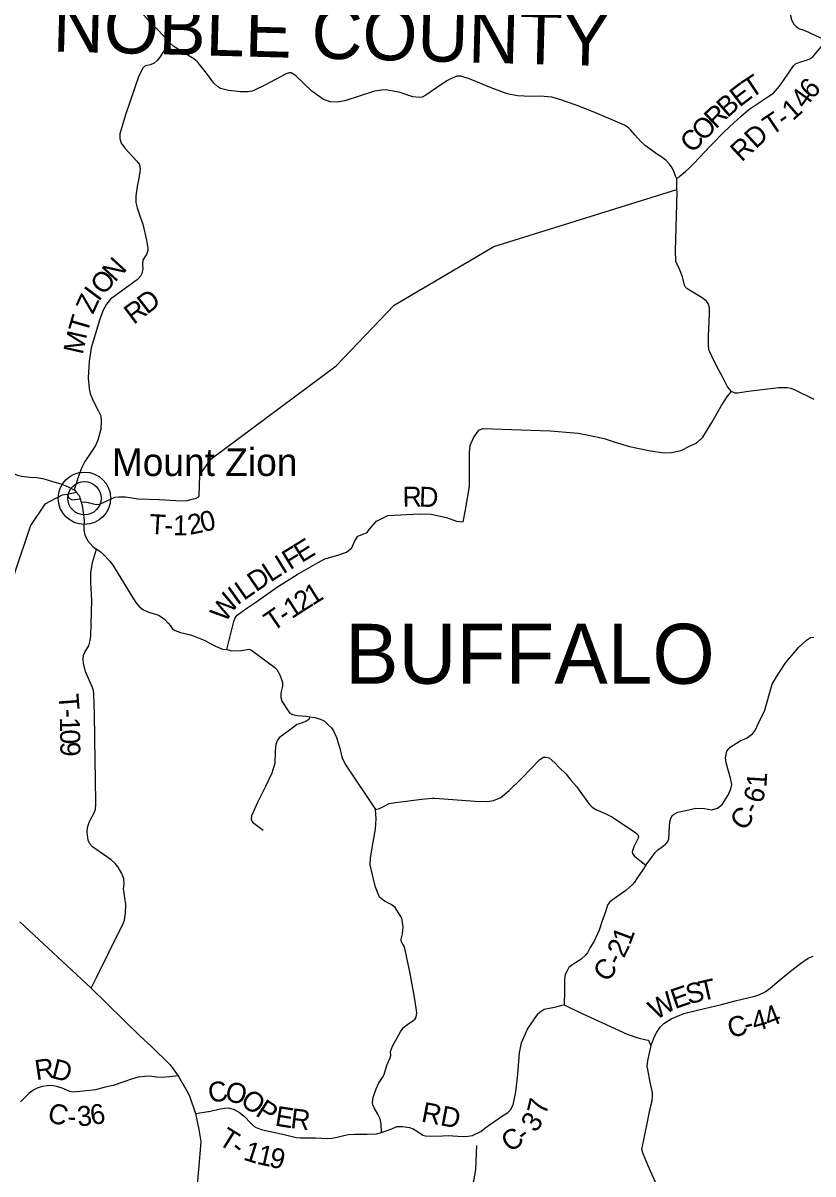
# Model space of a CAD drawing. Extents: x -22 to 431, y -18 to 160.
# Drawn here: x 324.981 to 327.228, y 153.438 to 156.71 of the extents above; entities that cross this region are included whole.
import ezdxf

# ---------------------------------------------------------------- set-up
doc = ezdxf.new("R2010")
doc.units = 0
for name, color, linetype in [('GM_X_Adjacent_County', 7, 'Continuous'), ('GM_X_Adjacent_County_Text', 7, 'Continuous'), ('GM_X_City_Street', 7, 'Continuous'), ('GM_X_City_Street_Text', 7, 'Continuous'), ('GM_X_County_Road', 7, 'Continuous'), ('GM_X_County_Road_Text', 7, 'Continuous'), ('GM_X_County_ROW', 7, 'Continuous'), ('GM_X_Minor_River_Text', 7, 'Continuous'), ('GM_X_Township_Road', 7, 'Continuous'), ('GM_X_Unincorporated_Text', 7, 'Continuous')]:
    doc.layers.add(name, color=color, linetype=linetype)

msp = doc.modelspace()

# ---------------------------------------------------------------- linework, layer by layer
at = {"layer": 'GM_X_Adjacent_County_Text'}
for points in [[(327.2309, 155.64), (327.1774, 155.6661), (327.1657, 155.6708), (327.1532, 155.6736), (327.1297, 155.6728), (327.0443, 155.6625), (327.0131, 155.658), (327.0056, 155.6584), (326.9958, 155.6627), (326.9909, 155.6681), (326.9846, 155.6758), (326.9701, 155.7048), (326.9542, 155.7342), (326.9409, 155.761), (326.9328, 155.7789), (326.9307, 155.7911), (326.9303, 155.8203), (326.933, 155.8836), (326.9336, 155.9007), (326.9318, 155.9076), (326.9296, 155.9129), (326.9244, 155.9209), (326.9124, 155.9291), (326.8763, 155.9508), (326.8688, 155.9558), (326.865, 155.9597), (326.8624, 155.9646), (326.8563, 155.9886), (326.8515, 156.0012), (326.8453, 156.0168), (326.8394, 156.0279), (326.8379, 156.0329), (326.8368, 156.0625), (326.8412, 156.2294), (326.841, 156.237), (326.8407, 156.2506), (326.8402, 156.267), (326.8369, 156.275), (326.8328, 156.286), (326.8269, 156.2983), (326.8199, 156.309), (326.8098, 156.3194), (326.7951, 156.3309), (326.7827, 156.3387), (326.7643, 156.3518), (326.7515, 156.3615), (326.7369, 156.3746), (326.7209, 156.3926), (326.71, 156.4053), (326.7033, 156.4122), (326.692, 156.4199), (326.6072, 156.4563), (326.554, 156.4767), (326.5083, 156.4929), (326.4849, 156.4996), (326.453, 156.5023), (326.4257, 156.5014), (326.3876, 156.5037), (326.3578, 156.5093), (326.3129, 156.5256), (326.2531, 156.5505), (326.2267, 156.5595), (326.215, 156.5592), (326.2002, 156.5529), (326.1865, 156.5455), (326.1572, 156.526), (326.1271, 156.5055), (326.1165, 156.4999), (326.1074, 156.4981), (326.0896, 156.5009), (326.0542, 156.5126), (326.0342, 156.517), (326.0135, 156.5202), (326.0006, 156.5192), (325.9813, 156.5164), (325.8967, 156.4895), (325.8736, 156.4852), (325.8555, 156.4858), (325.8355, 156.4928), (325.8029, 156.5166), (325.7572, 156.5599), (325.7485, 156.566), (325.7437, 156.5684), (325.7384, 156.5688), (325.7293, 156.5662), (325.6692, 156.5338), (325.6396, 156.519), (325.6327, 156.5164), (325.6218, 156.515), (325.5998, 156.5148), (325.5659, 156.5185), (325.5432, 156.5244), (325.5342, 156.5298), (325.5241, 156.5394), (325.5032, 156.5677), (325.4846, 156.5917), (325.4771, 156.6002), (325.467, 156.6086), (325.4407, 156.6248), (325.4106, 156.644), (325.3975, 156.6548), (325.3852, 156.6689), (325.3601, 156.6961), (325.3182, 156.7389)], [(324.78, 155.5591), (324.7845, 155.547), (324.79, 155.5302), (324.7951, 155.5181), (324.8026, 155.5055), (324.8157, 155.4944), (324.8401, 155.4816), (324.8714, 155.4669), (324.9022, 155.4537), (324.9477, 155.4324), (324.9658, 155.4247), (324.9768, 155.4219), (325.0005, 155.4194), (325.0206, 155.4181), (325.0376, 155.4152), (325.0628, 155.4078), (325.0922, 155.3992), (325.1095, 155.3918), (325.1197, 155.3871), (325.1266, 155.3827), (325.1334, 155.3754), (325.141, 155.3672), (325.1441, 155.3573), (325.1469, 155.3484)], [(325.1469, 155.3484), (325.1493, 155.3382), (325.1532, 155.3125), (325.155, 155.2978), (325.1542, 155.2784), (325.154, 155.2689), (325.1568, 155.2553), (325.1643, 155.2391), (325.1801, 155.2224), (325.1905, 155.2142), (325.1997, 155.2087), (325.2093, 155.2005), (325.2278, 155.1807), (325.2383, 155.1657), (325.2515, 155.1444), (325.2675, 155.1196), (325.2889, 155.084), (325.3022, 155.0626), (325.3111, 155.0525), (325.3222, 155.0428), (325.3409, 155.0341), (325.3618, 155.0291), (325.3687, 155.0259), (325.3837, 155.0151), (325.3937, 155.0043), (325.4003, 154.9961), (325.4057, 154.9886), (325.4141, 154.9834), (325.429, 154.9776), (325.4579, 154.9709), (325.4682, 154.967), (325.4964, 154.9561), (325.5289, 154.9385), (325.5488, 154.9301), (325.5605, 154.9288), (325.5753, 154.9256), (325.603, 154.9261), (325.6185, 154.9294), (325.6237, 154.9303), (325.6314, 154.927), (325.654, 154.9107), (325.6977, 154.8785), (325.7035, 154.8726), (325.7117, 154.8568), (325.7165, 154.8436), (325.7189, 154.8357), (325.7191, 154.8251), (325.7156, 154.8094), (325.7142, 154.8011), (325.7147, 154.7931), (325.7176, 154.7822), (325.7394, 154.7496), (325.7474, 154.7444), (325.7611, 154.742), (325.7869, 154.7398), (325.7967, 154.7381), (325.8108, 154.7361), (325.8275, 154.731), (325.839, 154.7259), (325.8486, 154.7162), (325.8583, 154.7062), (325.8641, 154.6979), (325.8731, 154.6791), (325.8827, 154.649), (325.8869, 154.6274), (325.8897, 154.6184), (325.8991, 154.6003), (325.9841, 154.4744), (325.9948, 154.4773), (326.0143, 154.4871), (326.0229, 154.491), (326.0407, 154.4944), (326.1151, 154.5033), (326.1439, 154.5061), (326.1526, 154.507), (326.2667, 154.4977), (326.3023, 154.4972), (326.3193, 154.5002), (326.34, 154.5085), (326.3635, 154.5283), (326.3989, 154.5627), (326.451, 154.6163), (326.4619, 154.623), (326.4676, 154.6234), (326.4774, 154.621), (326.4932, 154.6072), (326.5052, 154.5945), (326.5262, 154.5749), (326.5396, 154.5579), (326.5553, 154.5394), (326.5909, 154.4899), (326.5997, 154.4809), (326.61, 154.4741), (326.637, 154.4626), (326.6466, 154.4585), (326.6576, 154.4528), (326.7243, 154.4082), (326.73, 154.4021), (326.7316, 154.3976), (326.7309, 154.3926), (326.7185, 154.3679), (326.7133, 154.3538), (326.7141, 154.3496), (326.7202, 154.341), (326.7206, 154.3407)], [(326.8262, 154.455), (326.8263, 154.4552), (326.8271, 154.4571), (326.8332, 154.4613), (326.8434, 154.467), (326.8744, 154.4737), (326.8941, 154.4777), (326.9192, 154.4774), (326.9397, 154.4734), (326.9563, 154.4777), (326.9699, 154.4888), (326.9875, 154.5174), (326.9939, 154.5334), (326.9968, 154.5455), (326.9944, 154.5599), (326.9808, 154.6073), (326.9792, 154.6209), (326.9832, 154.6399), (326.9923, 154.6514), (327.021, 154.6694), (327.0384, 154.6771), (327.0553, 154.6894), (327.064, 154.7005), (327.0752, 154.7267), (327.0902, 154.7542), (327.112, 154.8302), (327.127, 154.8565), (327.1367, 154.8702), (327.151, 154.892), (327.1879, 154.9363), (327.2093, 154.9558), (327.2203, 154.9634), (327.2298, 154.9646)], [(326.7527, 154.3165), (326.7651, 154.3318), (326.7793, 154.352), (326.7861, 154.3596), (326.7993, 154.3685), (326.8095, 154.3765), (326.8151, 154.383), (326.8181, 154.3906), (326.8194, 154.4267), (326.8208, 154.4388), (326.8234, 154.4487), (326.8262, 154.455)], [(326.7206, 154.3407), (326.721, 154.3404), (326.7527, 154.3165), (326.7436, 154.3032), (326.729, 154.281), (326.72, 154.2677), (326.7144, 154.2612), (326.6951, 154.2444), (326.6634, 154.221), (326.6498, 154.2114), (326.6468, 154.2084), (326.6431, 154.2026), (326.6375, 154.1833), (326.6282, 154.1574), (326.6197, 154.1315), (326.6152, 154.1205), (326.6051, 154.0999), (326.5943, 154.0816), (326.5864, 154.0668), (326.5819, 154.0607), (326.5683, 154.0484), (326.5525, 154.0384), (326.5415, 154.0308), (326.5336, 154.025), (326.5283, 154.0159), (326.5235, 154.0056), (326.5213, 153.9919), (326.5216, 153.9589), (326.5203, 153.9187), (326.5257, 153.9157), (326.563, 153.8985), (326.6516, 153.8574), (326.6996, 153.8357), (326.7296, 153.8253), (326.7532, 153.8197), (326.7597, 153.8183), (326.767, 153.802), (326.764, 153.7914), (326.757, 153.7594), (326.7556, 153.7439), (326.7568, 153.7348), (326.7639, 153.6995), (326.7702, 153.67), (326.7707, 153.6601), (326.7696, 153.6449), (326.763, 153.6194), (326.7425, 153.5206), (326.7403, 153.5092), (326.7438, 153.496), (326.7581, 153.4619), (326.8097, 153.3476)], [(326.767, 153.802), (326.7718, 153.8138), (326.7774, 153.8294), (326.7834, 153.8412), (326.7935, 153.8553), (326.8037, 153.8656), (326.8248, 153.8791), (326.8608, 153.8941), (326.9032, 153.905), (326.9679, 153.9195), (327.0069, 153.9301), (327.0626, 153.9441), (327.0736, 153.9476), (327.0917, 153.9557), (327.1061, 153.966), (327.1313, 153.9882), (327.1634, 154.0143), (327.1921, 154.0369), (327.2136, 154.0518), (327.2279, 154.0576)], [(326.2829, 153.5588), (326.2938, 153.567), (326.305, 153.5756), (326.3226, 153.5884), (326.3421, 153.6012), (326.36, 153.6126), (326.3679, 153.6203), (326.3756, 153.6345), (326.3829, 153.6718), (326.3881, 153.7223), (326.3931, 153.7823), (326.399, 153.8109), (326.4158, 153.8499), (326.4464, 153.8948), (326.4547, 153.9014), (326.4637, 153.9065), (326.4972, 153.9135), (326.5131, 153.9182), (326.5203, 153.9187)], [(325.4221, 153.7171), (325.3987, 153.7141), (325.3745, 153.7128), (325.3609, 153.7138), (325.3408, 153.7159), (325.3264, 153.7154), (325.309, 153.713), (325.2894, 153.708), (325.2682, 153.6998), (325.238, 153.6893), (325.2153, 153.6846), (325.1877, 153.6776), (325.1522, 153.6731), (325.1242, 153.671), (325.1147, 153.6725), (325.093, 153.6818), (325.0763, 153.6869), (325.0619, 153.6895), (325.0498, 153.689), (325.0358, 153.6866), (325.0215, 153.6823), (325.012, 153.6773), (324.9977, 153.6666), (324.9744, 153.6429)], [(326.2484, 152.8999), (326.2484, 152.9001), (326.2493, 152.9074), (326.2474, 152.9225), (326.2394, 152.9506), (326.2367, 152.9711), (326.2382, 153.0116), (326.2416, 153.0492), (326.2427, 153.0666), (326.2434, 153.1561), (326.2422, 153.238), (326.2407, 153.2521), (326.2308, 153.2979), (326.2262, 153.3275), (326.2262, 153.3396), (326.2289, 153.3537), (326.2425, 153.3783), (326.2546, 153.3973), (326.2633, 153.4182), (326.2689, 153.4508), (326.2715, 153.5187)]]:
    msp.add_lwpolyline(points, dxfattribs=at)
at = {"layer": 'GM_X_County_Road'}
for points in [[(325.4665, 155.3574), (325.4721, 155.3588), (325.4822, 155.3643), (325.4841, 155.426), (325.516, 155.4716), (325.8717, 155.7354), (326.0364, 155.9078), (326.3201, 156.0747), (326.841, 156.237)], [(325.0761, 155.359), (325.0436, 155.342), (325.003, 155.2814), (324.9572, 155.1463), (324.9349, 155.0139), (324.8995, 154.871), (324.8735, 154.8425), (324.8277, 154.8155), (324.7381, 154.7797)], [(326.0012, 153.5563), (326, 153.5798), (325.9965, 153.5946), (325.9907, 153.6078), (325.98, 153.6263), (325.9761, 153.6347), (325.9749, 153.6415), (325.9767, 153.6551), (325.9856, 153.6802), (325.9924, 153.6958), (326.0036, 153.7126), (326.0085, 153.7206), (326.0125, 153.7343), (326.017, 153.7491), (326.0255, 153.7685), (326.027, 153.775), (326.0265, 153.7864), (326.0321, 153.8012), (326.0546, 153.8424), (326.0632, 153.8546), (326.0752, 153.8645), (326.0899, 153.8737), (326.0963, 153.8791), (326.0997, 153.8844), (326.1011, 153.8966), (326.0959, 153.9348), (326.0821, 154.0083), (326.0719, 154.0572), (326.066, 154.0841), (326.0614, 154.0916), (326.0565, 154.1003), (326.0564, 154.1056), (326.0605, 154.1212), (326.0626, 154.1409), (326.0582, 154.1652), (326.0487, 154.181), (326.0398, 154.1957), (326.028, 154.2044), (326.0094, 154.2133), (325.9953, 154.225), (325.9841, 154.2533), (325.9748, 154.2885), (325.9689, 154.3169), (325.9699, 154.3367), (325.9771, 154.3815), (325.9833, 154.4183), (325.9853, 154.4491), (325.9841, 154.4744)]]:
    msp.add_lwpolyline(points, dxfattribs=at)
at = {"layer": 'GM_X_County_ROW'}
msp.add_lwpolyline([(324.9719, 154.1547), (325.1741, 153.9674), (325.1752, 153.9663), (325.3131, 153.8306), (325.347, 153.8006), (325.4, 153.7483), (325.4221, 153.7171), (325.4479, 153.6724), (325.4548, 153.6603), (325.4717, 153.6102), (325.481, 153.5642), (325.4868, 153.5304), (325.4814, 153.4613), (325.4752, 153.3978)], dxfattribs=at)
at = {"layer": 'GM_X_Minor_River_Text'}
for points in [[(327.1474, 156.7858), (327.1525, 156.7737), (327.1568, 156.757), (327.1626, 156.7344), (327.1667, 156.7202), (327.1698, 156.7135), (327.1732, 156.707), (327.1796, 156.7001), (327.1873, 156.6948), (327.2044, 156.6886), (327.2352, 156.6744), (327.256, 156.665), (327.2665, 156.6603)], [(325.3975, 156.6548), (325.391, 156.6454), (325.3706, 156.6137), (325.3633, 156.6039), (325.3546, 156.5964), (325.3439, 156.5912), (325.3337, 156.5898), (325.3288, 156.5883), (325.3223, 156.582), (325.3103, 156.5601), (325.2729, 156.4494), (325.2565, 156.3953), (325.2564, 156.3824), (325.2608, 156.3684), (325.272, 156.3531), (325.3052, 156.3171), (325.309, 156.3126), (325.3123, 156.308), (325.3141, 156.2935), (325.3108, 156.2686), (325.306, 156.2451), (325.302, 156.2194), (325.3025, 156.2004), (325.3062, 156.1848), (325.3131, 156.1624), (325.322, 156.1388), (325.3325, 156.0928), (325.3364, 156.07), (325.3363, 156.0636), (325.3324, 156.0519), (325.3251, 156.0406), (325.3224, 156.0357), (325.3208, 156.0236), (325.3218, 156.011), (325.319, 155.9978), (325.3152, 155.9906), (325.3068, 155.9809), (325.2298, 155.9248), (325.2183, 155.9108), (325.2091, 155.8942), (325.1994, 155.8682), (325.1755, 155.7869), (325.1694, 155.7483), (325.1667, 155.7017), (325.1691, 155.6717), (325.1727, 155.6573), (325.1812, 155.636), (325.1953, 155.6085), (325.2023, 155.5933), (325.204, 155.5789), (325.2027, 155.5554), (325.194, 155.524), (325.1874, 155.5089), (325.1755, 155.4905), (325.1568, 155.4641), (325.1483, 155.4468), (325.1374, 155.4162), (325.1266, 155.3827)], [(327.1457, 156.5495), (327.1723, 156.5887), (327.1781, 156.5943), (327.1876, 156.5983), (327.2108, 156.606), (327.2188, 156.6086), (327.2276, 156.6145), (327.2419, 156.6314), (327.2665, 156.6603)], [(326.8402, 156.267), (326.8505, 156.2759), (326.8655, 156.2883), (326.8751, 156.2969), (326.8901, 156.3119), (326.9354, 156.3599), (326.975, 156.4011), (327.003, 156.4262), (327.0234, 156.4456), (327.0456, 156.4643), (327.0678, 156.48), (327.1022, 156.5019), (327.1156, 156.5112), (327.1329, 156.5307), (327.1457, 156.5495), (327.1457, 156.5495)], [(326.8974, 155.5172), (326.8977, 155.5174), (326.8995, 155.5183), (326.9144, 155.5325), (326.94, 155.575), (326.9676, 155.6229), (326.9846, 155.6496), (326.9958, 155.6627)], [(325.6666, 155.0803), (325.7025, 155.1054), (325.7606, 155.1421), (325.8202, 155.177), (325.8394, 155.1872), (325.8763, 155.1973), (325.9015, 155.2061), (325.9165, 155.2185), (325.9245, 155.238), (325.9337, 155.2518), (325.9502, 155.2578), (325.9596, 155.2614), (325.9655, 155.2706), (325.9863, 155.2945), (326.019, 155.3103), (326.1091, 155.3149), (326.1417, 155.3144), (326.1858, 155.3045), (326.2136, 155.2937), (326.2326, 155.2925), (326.2392, 155.3264), (326.2512, 155.3931), (326.2511, 155.4891), (326.2528, 155.5095), (326.2628, 155.5314), (326.2778, 155.5529), (326.2888, 155.5573), (326.48, 155.5513), (326.5597, 155.5439), (326.5892, 155.5386), (326.6338, 155.5293), (326.6652, 155.519), (326.7056, 155.506), (326.7661, 155.4942), (326.8043, 155.488), (326.8255, 155.4889), (326.8525, 155.4953), (326.8789, 155.5079), (326.8974, 155.5172)], [(325.1334, 155.3754), (325.107, 155.3703), (325.0924, 155.3676), (325.0764, 155.3592), (325.0761, 155.359)], [(325.107, 155.3703), (325.1127, 155.3598), (325.121, 155.355), (325.1441, 155.3573)], [(325.1469, 155.3484), (325.1564, 155.3486), (325.1662, 155.3469), (325.1807, 155.343), (325.1902, 155.3413), (325.1996, 155.3422), (325.2177, 155.3505), (325.2429, 155.3619), (325.2538, 155.3636), (325.2724, 155.3636), (325.3092, 155.3574), (325.3683, 155.3555), (325.4161, 155.3525), (325.4453, 155.3519), (325.4663, 155.3574), (325.4665, 155.3574)], [(325.1752, 153.9663), (325.1899, 153.997), (325.2251, 154.0682), (325.2661, 154.1505), (325.2701, 154.1597), (325.2727, 154.1794), (325.2742, 154.2049), (325.2712, 154.2226), (325.2687, 154.237), (325.267, 154.2487), (325.2687, 154.2624), (325.2684, 154.2772), (325.2628, 154.2927), (325.2519, 154.3107), (325.243, 154.3211), (325.2323, 154.3312), (325.1882, 154.3619), (325.1793, 154.3685), (325.1716, 154.3764), (325.1665, 154.3869), (325.1635, 154.41), (325.1644, 154.4229), (325.1709, 154.4404), (325.1845, 154.4669), (325.1873, 154.4753), (325.1886, 154.4897), (325.1877, 154.5633), (325.1869, 154.6114), (325.1842, 154.7449), (325.1832, 154.8018), (325.1815, 154.8127), (325.1791, 154.8214), (325.1704, 154.8402), (325.1594, 154.8666), (325.1533, 154.89), (325.152, 154.9021), (325.1529, 154.9131), (325.1584, 154.9238), (325.1683, 154.9399), (325.1723, 154.9544), (325.1739, 154.9685), (325.1767, 155.0698), (325.174, 155.1187), (325.1746, 155.1468), (325.179, 155.1761), (325.1905, 155.2142)], [(325.5605, 154.9288), (325.5659, 154.9486), (325.5807, 155.0088), (325.5847, 155.0191), (325.5903, 155.0272), (325.6048, 155.0377), (325.6206, 155.0482), (325.6408, 155.0622), (325.6664, 155.0802), (325.6666, 155.0803)], [(325.7967, 154.7381), (325.7946, 154.7304), (325.7852, 154.7246), (325.7668, 154.7182), (325.7604, 154.7158), (325.7495, 154.7076), (325.7211, 154.6866), (325.7107, 154.6789), (325.7051, 154.6716), (325.7004, 154.659), (325.6984, 154.6411), (325.6971, 154.6054), (325.695, 154.5963), (325.6893, 154.578), (325.671, 154.5401), (325.6483, 154.4942), (325.6315, 154.4567), (325.6302, 154.4472), (325.6338, 154.4382), (325.6641, 154.4156)], [(325.4717, 153.6102), (325.4961, 153.6141), (325.5142, 153.6171), (325.5418, 153.6233), (325.5607, 153.6263), (325.5694, 153.6257), (325.582, 153.6213), (325.5973, 153.6133), (325.6107, 153.6029), (325.6296, 153.5827), (325.6373, 153.5742), (325.6442, 153.5701), (325.6587, 153.5643), (325.7237, 153.5507), (325.7583, 153.5422), (325.7701, 153.5413), (325.8129, 153.5405), (325.8474, 153.5392), (325.8595, 153.5395), (325.8746, 153.5428), (325.8972, 153.5489), (325.907, 153.5506), (325.9237, 153.5509), (325.9596, 153.5511), (325.9861, 153.5527), (326.0012, 153.5563), (326.0302, 153.5664), (326.0445, 153.5728), (326.0611, 153.5727), (326.0805, 153.5704), (326.0912, 153.566), (326.1034, 153.5586), (326.1184, 153.5483), (326.126, 153.5462), (326.1415, 153.5457), (326.1745, 153.5467), (326.1904, 153.5473), (326.2036, 153.5468), (326.2324, 153.5447), (326.2464, 153.5453), (326.2597, 153.5478), (326.2829, 153.5588)]]:
    msp.add_lwpolyline(points, dxfattribs=at)
at = {"layer": 'GM_X_Township_Road'}
for radius in [0.0744, 0.0472]:
    msp.add_circle((325.156, 155.3592), radius, dxfattribs=at)

# ---------------------------------------------------------------- texts
at = {"layer": 'GM_X_Adjacent_County'}
msp.add_text('Mount Zion', height=0.07891, rotation=0, dxfattribs=at).set_placement((325.2339, 155.4225))
at = {"layer": 'GM_X_City_Street'}
for s, rotation, p in [('1', 86.1289, (327.095, 154.5363)), ('6', 73.1837, (327.0823, 154.489)), ('C', 50.4338, (327.0301, 154.4108)), ('-', 61.9541, (327.0667, 154.4572)), ('1', 69.6432, (326.7077, 154.0868)), ('2', 63.873, (326.6899, 154.0497)), ('-', 62.5198, (326.6784, 154.0277)), ('C', 49.3923, (326.6401, 153.9805)), ('T', 12.7566, (326.9107, 153.9292)), ('W', 30.5301, (326.7809, 153.8744)), ('E', 18.874, (326.8348, 153.9065)), ('S', 14.1999, (326.8739, 153.9199)), ('4', 15.9741, (327.0622, 153.8421)), ('4', 22.0714, (327.1021, 153.8539)), ('C', 14.4215, (326.9928, 153.8241)), ('-', 14.7411, (327.0383, 153.8358)), ('R', 8.3189, (325.019, 153.7046)), ('D', 346.0159, (325.0594, 153.7116)), ('C', 345.1591, (325.0477, 153.5877)), ('3', 5.0048, (325.1375, 153.5732)), ('6', 9.4377, (325.1771, 153.5768)), ('7', 77.0313, (326.4692, 153.6039)), ('-', 358.2349, (325.1068, 153.5737)), ('3', 54.5647, (326.439, 153.5533)), ('C', 33.6608, (326.3651, 153.4981)), ('-', 35.8265, (326.4059, 153.5253))]:
    msp.add_text(s, height=0.0568, rotation=rotation, dxfattribs=at).set_placement(p)
at = {"layer": 'GM_X_City_Street_Text'}
for s, height, rotation, p in [('E', 0.0568, 37.3653, (327.0187, 156.4694)), ('T', 0.0568, 33.5878, (327.0517, 156.4946)), ('6', 0.0568, 48.181, (327.2253, 156.491)), ('B', 0.0568, 41.5924, (326.9847, 156.4391)), ('4', 0.0568, 54.0246, (327.2057, 156.4638)), ('1', 0.0568, 41.4337, (327.1703, 156.4306)), ('R', 0.0568, 43.5482, (326.9512, 156.4073)), ('T', 0.0568, 34.0395, (327.1097, 156.3885)), ('-', 0.0568, 35.0271, (327.1458, 156.4129)), ('O', 0.0568, 46.0973, (326.917, 156.3717)), ('RD', 0.05682, 42.8433, (327.0249, 156.3134)), ('C', 0.0568, 46.565, (326.885, 156.3379)), ('N', 0.0568, 47.4967, (325.243, 155.9711)), ('O', 0.0568, 47.9378, (325.2096, 155.934)), ('I', 0.0568, 53.3034, (325.1966, 155.9164)), ('Z', 0.0568, 65.6241, (325.1806, 155.8805)), ('R', 0.0568, 36.7918, (325.2959, 155.8515)), ('D', 0.0568, 37.9522, (325.3342, 155.8802)), ('T', 0.0568, 73.7461, (325.1641, 155.825)), ('M', 0.0568, 77.2655, (325.1508, 155.7658)), ('R', 0.0568, 1.1319, (326.0611, 155.3347)), ('D', 0.0568, 357.8831, (326.1069, 155.3356)), ('T', 0.0568, 356.7153, (325.3392, 155.2579)), ('1', 0.0568, 359.0844, (325.4075, 155.2542)), ('2', 0.0568, 11.2951, (325.4556, 155.2549)), ('0', 0.0568, 13.7065, (325.4925, 155.2623)), ('-', 0.0568, 357.1164, (325.3821, 155.2555)), ('E', 0.0568, 31.8385, (325.7736, 155.1743)), ('F', 0.0568, 31.407, (325.7405, 155.1541)), ('L', 0.0568, 32.5905, (325.685, 155.1192)), ('I', 0.0568, 31.5073, (325.7206, 155.1419)), ('D', 0.0568, 34.2993, (325.6441, 155.0913)), ('I', 0.0568, 35.3616, (325.5904, 155.0536)), ('L', 0.0568, 34.9179, (325.6094, 155.067)), ('1', 0.0568, 31.9866, (325.8044, 155.0529)), ('W', 0.0568, 54.9647, (325.5563, 155.0033)), ('1', 0.0568, 33.0839, (325.7457, 155.0152)), ('2', 0.0568, 32.3231, (325.7749, 155.0342)), ('T', 0.0568, 34.4152, (325.6916, 154.9784)), ('-', 0.0568, 33.8286, (325.7265, 155.0024)), ('T', 0.0568, 274.2939, (325.0823, 154.8013)), ('-', 0.0568, 271.1007, (325.0854, 154.7598)), ('1', 0.0568, 271.1068, (325.0859, 154.7364)), ('0', 0.0568, 271.1033, (325.0866, 154.7015)), ('9', 0.0568, 271.1068, (325.0872, 154.6665)), ('C', 0.0568, 10.7848, (325.5134, 153.6391)), ('O', 0.0568, 346.2703, (325.5528, 153.648)), ('O', 0.0568, 322.7717, (325.5959, 153.6388)), ('P', 0.0568, 327.2161, (325.6396, 153.6058)), ('E', 0.0568, 350.9304, (325.6957, 153.5759)), ('RD', 0.05682, 349.0774, (326.1115, 153.5876)), ('R', 0.0568, 353.0718, (325.74, 153.5689)), ('T', 0.0568, 328.1205, (325.5334, 153.525)), ('-', 0.0568, 322.6789, (325.5683, 153.5033)), ('1', 0.0568, 342.1147, (325.6054, 153.4795)), ('1', 0.0568, 347.241, (325.644, 153.4673)), ('9', 0.0568, 347.507, (325.6785, 153.4595))]:
    msp.add_text(s, height=height, rotation=rotation, dxfattribs=at).set_placement(p)
at = {"layer": 'GM_X_County_Road_Text'}
msp.add_text('BUFFALO', height=0.17045, rotation=0, dxfattribs=at).set_placement((325.8971, 154.8318))
at = {"layer": 'GM_X_Unincorporated_Text'}
msp.add_text('NOBLE COUNTY', height=0.15, rotation=358.4869, dxfattribs=at).set_placement((325.0648, 156.6296))

doc.saveas('drawing.dxf')
